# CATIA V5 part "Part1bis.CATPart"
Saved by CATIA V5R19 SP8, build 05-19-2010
Part number: Part1bis
Bounding box of the stored display mesh (mm): x 0 to 410, y -90 to 20, z -73.691 to 6.309
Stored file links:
  G:\EU_thinkMotion\CFAO_2010\SIL_groupe2\SIL_groupe2\A reprendre\fnongaibaa\fnongaibaa\Part1bis.CATPart
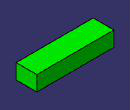
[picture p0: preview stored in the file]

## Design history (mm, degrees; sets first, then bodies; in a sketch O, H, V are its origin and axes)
Body1 (main body)
  Sketch1 on yz-plane, origin (0, 0, 0), H (0, 1, 0), V (0, 0, 1)
    line L1 (-90, 6.3085) -> (20, 6.3085)
    line L2 (20, 6.3085) -> (20, -73.6915)
    line L3 (20, -73.6915) -> (-90, -73.6915)
    line L4 (-90, -73.6915) -> (-90, 6.3085)
    length L2 = 80
    length L1 = 110
    horizontal: L1 H, L3 H
    vertical: L2 V, L4 V
  Pad1: profile Sketch1, direction (1, 0, 0), length 410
